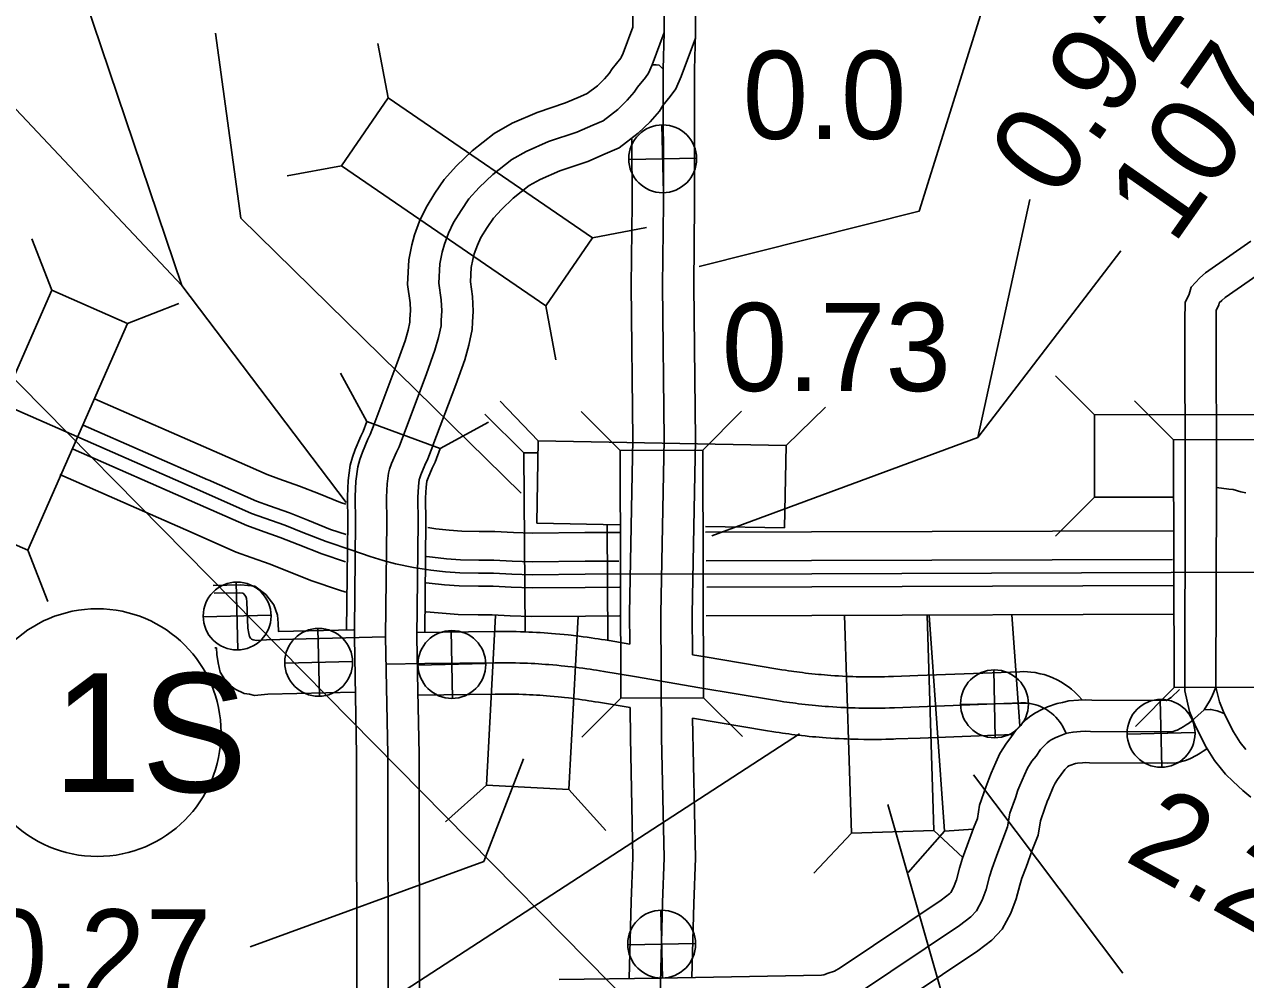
# Model space of a CAD drawing. Extents: x 31699 to 244310, y -8841 to 11474.
# Drawn here: x 100385.5 to 100776, y 2787.2 to 3092.6 of the extents above; entities that cross this region are included whole.
import ezdxf

# ---------------------------------------------------------------- set-up
doc = ezdxf.new("R2010")
doc.units = 0
for name, color, linetype in [('B_Logo', 7, 'Continuous'), ('G-ANNO-TEXT', 7, 'Continuous'), ('Level 21', 7, 'Continuous'), ('Level 48', 7, 'Continuous'), ('New Level (0)', 7, 'Continuous'), ('R_Border Notes', 7, 'Continuous'), ('R_XS_EARTHWORK_STAGE1', 7, 'Continuous'), ('R_XS_EARTHWORK_STAGE2', 7, 'Continuous'), ('S_WALL', 7, 'Continuous'), ('S_WALL_ANNOT', 7, 'Continuous')]:
    doc.layers.add(name, color=color, linetype=linetype)

msp = doc.modelspace()

# ---------------------------------------------------------------- linework, layer by layer
at = {"layer": 'B_Logo'}
for points in [[(100501.85, 2777.7), (100501.71, 2859.16), (100501.02, 2896.74), (100501.41, 2933.6), (100501.3, 2941.48), (100501.5, 2945.69), (100501.92, 2949.1), (100502.3, 2950.37), (100502.94, 2952.19), (100504.48, 2955.82), (100505.32, 2957.56), (100514.03, 2980.87), (100516.79, 2988.39), (100517.92, 2992.48), (100518.73, 2996.23), (100518.78, 2997.9), (100519, 3001.05), (100518.81, 3004.58), (100518.07, 3009.85), (100518.38, 3016.06), (100519.12, 3019.81), (100519.82, 3022.29), (100521.09, 3025.85), (100522.71, 3029.28), (100525.12, 3033.13), (100527.66, 3036.84), (100530.87, 3040.43), (100535.27, 3044.64), (100541.32, 3049.4), (100545.95, 3052.01), (100553.09, 3055.13), (100562.1, 3058.14), (100567.27, 3060.36), (100570.57, 3061.82), (100575.25, 3065.43), (100578.27, 3068.35), (100580.5, 3070.92), (100581.54, 3072.54), (100584.09, 3075.65), (100585.07, 3077), (100586.23, 3079.69), (100590.07, 3089.96), (100589.99, 3104.52)], [(100588.68, 2777.59), (100589.51, 2811.79), (100590.1, 2826.09), (100589.26, 2864.6), (100589.01, 2904.13), (100590.06, 2959.83), (100589.53, 3009.1), (100589.81, 3035.34), (100589.71, 3078.34), (100590.07, 3089.96)], [(100589.71, 3078.34), (100588.42, 3079.59), (100587.56, 3079.71), (100586.23, 3079.69)], [(100783.36, 3015.01), (100769.38, 3005.31), (100768.33, 3004.36), (100767.54, 3003.55), (100767.36, 3002.81), (100766.58, 3001.26), (100766.56, 2998.06), (100766.62, 2944.57), (100766.49, 2880.67), (100767.63, 2875.95), (100769.08, 2872.3), (100772.1, 2866.4), (100774.21, 2863.03), (100776.04, 2860.79)], [(100348.06, 2984.62), (100442.54, 2943.16)], [(100776.03, 2942.78), (100774.49, 2943.09), (100772.02, 2943.86), (100770.62, 2944.04), (100766.62, 2944.57)], [(100780.93, 2917.42), (100637.24, 2916.97), (100564.79, 2916.77), (100547.88, 2916.63), (100541.35, 2916.8), (100535.48, 2917.11), (100530.75, 2917.17), (100524.76, 2917.27), (100520.16, 2917.6), (100515.42, 2918.06), (100509.95, 2918.91), (100504.14, 2920.09), (100500.26, 2921.23), (100496.11, 2922.5), (100490.16, 2924.48), (100481.99, 2927.22), (100474.56, 2930.17), (100468.8, 2932.49), (100462.44, 2934.72), (100458.15, 2936.26), (100442.54, 2943.16)], [(100501.02, 2896.74), (100462.88, 2895.87), (100459.75, 2895.62), (100459.15, 2895.74), (100458.68, 2895.8), (100458.15, 2896.06), (100457.81, 2896.32), (100457.47, 2896.85), (100457.26, 2897.85), (100456.96, 2899.58), (100456.64, 2907.99), (100456.56, 2909.06), (100456.35, 2909.66), (100455.94, 2910.18), (100455.67, 2910.51), (100455.33, 2910.78), (100454.27, 2910.89), (100446.15, 2910.7)], [(100501.05, 2888.02), (100513.58, 2888.2), (100535.97, 2888.47), (100537.22, 2888.48), (100538.34, 2888.48), (100539.43, 2888.48), (100540.49, 2888.47), (100541.35, 2888.46), (100542.55, 2888.44), (100543.88, 2888.4), (100545.23, 2888.36), (100546.38, 2888.31), (100547.54, 2888.26), (100548.67, 2888.2), (100549.86, 2888.13), (100550.98, 2888.06), (100552.11, 2887.98), (100553.24, 2887.9), (100554.46, 2887.8), (100555.79, 2887.68), (100557.12, 2887.55), (100558.27, 2887.44), (100559.27, 2887.33), (100560.62, 2887.17), (100561.68, 2887.05), (100562.86, 2886.9), (100564.06, 2886.74), (100565.3, 2886.56), (100566.41, 2886.4), (100567.49, 2886.24), (100568.46, 2886.09), (100569.57, 2885.9), (100570.78, 2885.7), (100580.63, 2884.04), (100601.52, 2880.52), (100624.73, 2876.61), (100624.73, 2876.61), (100626.1, 2876.39), (100627.31, 2876.2), (100628.33, 2876.04), (100629.3, 2875.9), (100630.19, 2875.77), (100631.2, 2875.64), (100632.1, 2875.52), (100633.03, 2875.4), (100634.05, 2875.28), (100635.13, 2875.15), (100636.22, 2875.03), (100637.39, 2874.91), (100638.46, 2874.81), (100639.41, 2874.72), (100640.48, 2874.63), (100641.5, 2874.55), (100642.59, 2874.46), (100643.97, 2874.37), (100645.26, 2874.29), (100646.56, 2874.22), (100648, 2874.15), (100648.82, 2874.11), (100650.02, 2874.07), (100651.17, 2874.03), (100652.31, 2874), (100654, 2873.98), (100655.77, 2873.96), (100657.07, 2873.96), (100658.18, 2873.97), (100659.39, 2873.98), (100660.72, 2874.01), (100662.1, 2874.04), (100663.09, 2874.08), (100663.73, 2874.1), (100671.57, 2874.4), (100704.09, 2875.64), (100704.88, 2875.65), (100705.59, 2875.62), (100706.24, 2875.57), (100707, 2875.47), (100708.01, 2875.24), (100708.85, 2875.05), (100709.59, 2874.8), (100710.34, 2874.49), (100711.2, 2874.1), (100712.04, 2873.64), (100712.71, 2873.22), (100713.31, 2872.81), (100713.87, 2872.36), (100714.6, 2871.72), (100715.27, 2871.09), (100715.89, 2870.39), (100716.45, 2869.71), (100716.99, 2868.91), (100717.49, 2868.13), (100718.52, 2866.11)], [(100766.49, 2880.67), (100765.14, 2877.58), (100764.43, 2876.17), (100762.67, 2873.47), (100758.66, 2869.8), (100758.07, 2869.32), (100757.01, 2868.64), (100756.02, 2868.02), (100755.3, 2867.54), (100754.11, 2866.92), (100753.71, 2866.78), (100752.45, 2866.43), (100750.85, 2866.41), (100726.41, 2866.49), (100724.81, 2866.6), (100723.22, 2866.51), (100720.82, 2866.33), (100719.49, 2866.05), (100718.5, 2865.83), (100716.38, 2865.06), (100715.12, 2864.51), (100713.8, 2863.82), (100713.14, 2863.41), (100712.48, 2862.86), (100711.63, 2862.05), (100710.38, 2860.7), (100708.95, 2858.67), (100707.64, 2856.98), (100706.21, 2854.75), (100705.31, 2852.67), (100703.83, 2849.24), (100703.18, 2847.7), (100702.35, 2845.35), (100700.63, 2840.44), (100699.89, 2836.03), (100698.35, 2832.06), (100696.37, 2826.62), (100694.96, 2822.79), (100694.13, 2820.11), (100693.06, 2816.02), (100691.72, 2812.53), (100689.97, 2809.16), (100688.13, 2807.26), (100684.51, 2804.47), (100651.54, 2782.38)], [(100769.08, 2872.3), (100766.87, 2873.13), (100765.8, 2873.38), (100765, 2873.5), (100764.6, 2873.5), (100762.67, 2873.47)]]:
    msp.add_lwpolyline(points, dxfattribs=at)
at = {"layer": 'G-ANNO-TEXT'}
msp.add_line((100633.38, 2865.75), (100310.14, 2655.9), dxfattribs=at)
msp.add_lwpolyline([(100601.26, 3015.16), (100671.57, 3032.86), (100704.46, 3137.9)], dxfattribs=at)
at = {"layer": 'Level 21'}
for p, q in [((100589.84, 3038.78), (100589.34, 3060.48)), ((100578.74, 3049.38), (100600.44, 3049.88)), ((100453.77, 2892.57), (100453.27, 2914.27)), ((100442.67, 2903.17), (100464.37, 2903.67)), ((100479.87, 2877.77), (100479.37, 2899.47)), ((100522.43, 2877.1), (100521.93, 2898.8)), ((100468.78, 2888.37), (100490.47, 2888.87)), ((100511.33, 2887.7), (100533.02, 2888.2)), ((100695.93, 2864.49), (100695.43, 2886.19)), ((100684.83, 2875.09), (100706.53, 2875.59)), ((100749.19, 2855.09), (100748.68, 2876.78)), ((100738.09, 2865.69), (100759.78, 2866.19)), ((100589.53, 2787.67), (100589.03, 2809.37)), ((100578.43, 2798.27), (100600.13, 2798.77))]:
    msp.add_line(p, q, dxfattribs=at)
for centre in [(100589.59, 3049.63), (100453.52, 2903.42), (100479.62, 2888.62), (100522.18, 2887.95), (100695.68, 2875.34), (100748.94, 2865.94), (100589.28, 2798.52)]:
    msp.add_circle(centre, 10.85, dxfattribs=at)
at = {"layer": 'Level 48'}
msp.add_line((100000.09, 3366.76), (102655.5, 673.93), dxfattribs=at)
at = {"layer": 'New Level (0)'}
for points in [[(100407.92, 2972.91), (100447.9, 2955.37)], [(100404.26, 2964.51), (100444.21, 2946.97)], [(100401.08, 2956.81), (100440.86, 2939.34)], [(100488.27, 2939.17), (100486.58, 2939.74), (100479.51, 2942.56), (100473.5, 2944.97), (100466.9, 2947.29), (100463.1, 2948.65), (100447.93, 2955.35)], [(100396.86, 2948.65), (100437.18, 2930.95)], [(100488.38, 2929.47), (100483.43, 2931.13), (100476.11, 2934.04), (100470.27, 2936.39), (100463.83, 2938.65), (100459.7, 2940.13), (100444.22, 2946.97)], [(100488.22, 2920.73), (100480.56, 2923.3), (100473.01, 2926.3), (100467.33, 2928.59), (100461.05, 2930.8), (100456.61, 2932.39), (100440.85, 2939.35)], [(100488.33, 2911.03), (100485.94, 2911.83), (100477.41, 2914.69), (100469.61, 2917.79), (100464.1, 2920.01), (100457.98, 2922.16), (100453.21, 2923.87), (100437.15, 2930.96)], [(100576.1, 2930.13), (100564.72, 2930.1), (100547.99, 2929.97), (100541.87, 2930.12), (100535.92, 2930.44), (100530.96, 2930.5), (100525.35, 2930.6), (100521.28, 2930.89), (100517.09, 2931.3), (100514.52, 2931.69)], [(100752.76, 2930.67), (100637.2, 2930.3), (100603.32, 2930.21)], [(100575.56, 2920.96), (100564.77, 2920.93), (100547.91, 2920.8), (100541.51, 2920.96), (100535.62, 2921.27), (100530.82, 2921.33), (100524.94, 2921.44), (100520.51, 2921.75), (100515.95, 2922.2), (100514.1, 2922.48)], [(100752.58, 2921.5), (100637.22, 2921.14), (100603.5, 2921.04)], [(100575.74, 2912.63), (100564.81, 2912.6), (100547.84, 2912.47), (100541.19, 2912.64), (100535.35, 2912.94), (100530.69, 2913), (100524.57, 2913.11), (100519.81, 2913.45), (100514.9, 2913.93), (100513.95, 2914.07)], [(100752.76, 2913.17), (100637.25, 2912.8), (100603.68, 2912.71)], [(100575.74, 2903.46), (100564.86, 2903.43), (100547.76, 2903.3), (100540.83, 2903.47), (100535.05, 2903.78), (100530.55, 2903.84), (100524.17, 2903.95), (100519.04, 2904.31), (100513.94, 2904.81)], [(100752.93, 2904), (100637.28, 2903.64), (100603.5, 2903.54)]]:
    msp.add_lwpolyline(points, dxfattribs=at)
at = {"layer": 'R_Border Notes'}
msp.add_circle((100408.8, 2866.15), 39.6, dxfattribs=at)
at = {"layer": 'R_XS_EARTHWORK_STAGE1'}
for p, q in [((100501.8, 3069.16), (100498.56, 3086.46)), ((100486.88, 3047.38), (100469.58, 3044.15)), ((100567.15, 3024.41), (100584.45, 3027.65)), ((100394.27, 3007.59), (100387.87, 3023.99)), ((100418.44, 2996.98), (100434.84, 3003.38)), ((100552.23, 3002.63), (100555.46, 2985.33)), ((100494.99, 2965.63), (100486.56, 2981.08)), ((100727.6, 2967.81), (100715.15, 2980.24)), ((100549.83, 2959.48), (100537.62, 2972.16)), ((100752.9, 2959.8), (100740.42, 2972.21)), ((100545.23, 2955.6), (100532.68, 2967.95)), ((100575.98, 2956.4), (100563.5, 2968.81)), ((100602.38, 2956.47), (100614.79, 2968.95)), ((100629.02, 2958), (100641.69, 2970.21)), ((100806.8, 2967.89), (100727.6, 2967.81)), ((100727.6, 2967.81), (100727.63, 2941.41)), ((100494.99, 2965.63), (100518.46, 2957.02)), ((100518.46, 2957.02), (100533.91, 2965.44)), ((100549.83, 2959.48), (100549.34, 2933.09)), ((100629.02, 2958), (100549.83, 2959.48)), ((100549.42, 2955.64), (100545.23, 2955.6)), ((100545.23, 2955.6), (100545.67, 2898.42)), ((100628.52, 2931.6), (100629.02, 2958)), ((100727.63, 2941.41), (100715.2, 2928.95)), ((100727.63, 2941.41), (100753.11, 2941.43)), ((100549.34, 2933.09), (100575.92, 2932.59)), ((100572.1, 2895.64), (100571.81, 2932.4)), ((100603.32, 2932.08), (100628.52, 2931.6)), ((100386.61, 2924.46), (100393, 2908.06)), ((100753.15, 2880.6), (100740.75, 2868.12)), ((100576.2, 2877.2), (100563.79, 2864.72)), ((100602.6, 2877.27), (100615.08, 2864.86)), ((100533.25, 2849.37), (100520.16, 2837.61)), ((100559.62, 2847.96), (100571.37, 2834.86)), ((100679.66, 2834.67), (100668.12, 2821.38)), ((100676.33, 2834.87), (100685.56, 2826.2)), ((100649.94, 2834.04), (100637.89, 2821.22))]:
    msp.add_line(p, q, dxfattribs=at)
for points in [[(100567.15, 3024.41), (100501.8, 3069.16), (100486.88, 3047.38), (100552.23, 3002.63)], [(100386.61, 2924.46), (100418.44, 2996.98), (100394.27, 3007.59), (100362.43, 2935.07)], [(100752.9, 2959.8), (100753.15, 2880.6), (100779.55, 2880.68), (100779.3, 2959.88)], [(100575.98, 2956.4), (100576.2, 2877.2), (100602.6, 2877.27), (100602.38, 2956.47)]]:
    msp.add_lwpolyline(points, close=True, dxfattribs=at)
for points in [[(100488.55, 2898.94), (100488.91, 2933.57), (100488.79, 2941.69), (100489.04, 2946.75), (100489.64, 2951.66), (100490.41, 2954.24), (100491.28, 2956.72), (100493.09, 2960.97), (100493.81, 2962.47), (100494.99, 2965.63)], [(100513.54, 2898.2), (100513.91, 2933.63), (100513.8, 2941.27), (100513.96, 2944.63), (100514.19, 2946.53), (100514.59, 2947.66), (100515.87, 2950.66), (100516.83, 2952.66), (100518.46, 2957.02)], [(100536.17, 2903.59), (100533.25, 2849.37), (100559.62, 2847.96), (100562.59, 2903.42)], [(100647.76, 2903.67), (100649.94, 2834.04), (100676.33, 2834.87), (100674.17, 2903.75)], [(100674.78, 2903.75), (100679.66, 2834.67), (100688.89, 2835.32)], [(100703.75, 2868.29), (100701.24, 2903.84)]]:
    msp.add_lwpolyline(points, dxfattribs=at)
at = {"layer": 'R_XS_EARTHWORK_STAGE2'}
for points in [[(100497.35, 2964.82), (100504.65, 2984.34), (100507.26, 2991.46), (100508.21, 2994.88), (100508.76, 2997.43), (100508.78, 2998.38), (100508.98, 3001.13), (100508.85, 3003.62), (100508.03, 3009.39), (100508.42, 3017.29), (100509.39, 3022.14), (100510.28, 3025.34), (100511.84, 3029.68), (100513.92, 3034.08), (100516.75, 3038.61), (100519.77, 3043.02), (100523.67, 3047.38), (100528.7, 3052.19), (100535.74, 3057.74), (100541.48, 3060.97), (100549.5, 3064.47), (100558.54, 3067.5), (100563.28, 3069.53), (100565.43, 3070.48), (100568.7, 3073), (100571, 3075.23), (100572.47, 3076.93), (100573.44, 3078.43), (100576.17, 3081.76), (100576.32, 3081.97), (100576.95, 3083.42), (100580.06, 3091.75), (100579.99, 3104.48)], [(100516.14, 2957.95), (100523.41, 2977.4), (100526.31, 2985.33), (100527.64, 2990.08), (100528.71, 2995.04), (100528.77, 2997.43), (100529.01, 3000.96), (100528.77, 3005.55), (100528.1, 3010.3), (100528.33, 3014.83), (100528.85, 3017.48), (100529.35, 3019.25), (100530.34, 3022.02), (100531.5, 3024.48), (100533.48, 3027.64), (100535.54, 3030.65), (100538.06, 3033.47), (100541.83, 3037.08), (100546.91, 3041.07), (100550.42, 3043.05), (100556.68, 3045.79), (100565.67, 3048.79), (100571.25, 3051.19), (100575.72, 3053.15), (100581.8, 3057.85), (100585.54, 3061.47), (100588.52, 3064.91), (100589.63, 3066.64), (100592.01, 3069.54), (100593.81, 3072.03), (100595.51, 3075.96), (100600.08, 3088.18), (100599.99, 3104.55)], [(100599.1, 2891.07), (100599.01, 2904.06), (100600.06, 2959.79), (100599.53, 3009.1), (100599.81, 3035.3), (100599.71, 3078.2), (100600.07, 3089.65)], [(100579.07, 2894.44), (100579.01, 2904.19), (100580.06, 2959.87), (100579.53, 3009.1), (100579.81, 3035.38), (100579.76, 3055.88)], [(100777.67, 3023.24), (100763.15, 3013.16), (100761.38, 3011.55), (100758.51, 3008.59), (100757.93, 3006.33), (100756.59, 3003.66), (100756.56, 2998.08), (100756.62, 2944.58), (100756.49, 2879.5), (100758.07, 2872.92), (100759.96, 2868.16), (100763.39, 2861.46), (100766.07, 2857.19), (100768.26, 2854.5), (100769.57, 2852.87), (100772.02, 2850.49), (100775.07, 2847.6), (100777.62, 2845.47)], [(100491.05, 2898.91), (100491.41, 2933.58), (100491.29, 2941.65), (100491.53, 2946.53), (100492.09, 2951.15), (100492.78, 2953.47), (100493.61, 2955.81), (100495.37, 2959.94), (100496.11, 2961.49), (100497.33, 2964.76)], [(100511.34, 2879.38), (100511.02, 2896.77), (100511.41, 2933.62), (100511.3, 2941.31), (100511.47, 2944.84), (100511.74, 2947.05), (100511.81, 2947.28), (100512.26, 2948.56), (100513.59, 2951.69), (100514.53, 2953.64), (100516.12, 2957.89)], [(100490.77, 2899.04), (100466.73, 2898.49), (100466.63, 2901.1), (100466.43, 2903.66), (100465.26, 2907.02), (100463.76, 2908.95), (100462.69, 2910.26), (100459.24, 2912.94), (100454.69, 2913.44), (100445.91, 2913.23)], [(100497.38, 2702.46), (100491.67, 2703.63), (100491.85, 2777.7), (100491.71, 2859.06), (100491.02, 2896.7), (100491.05, 2898.91)], [(100511, 2898.17), (100535.87, 2898.47), (100537.17, 2898.48), (100538.34, 2898.48), (100539.49, 2898.48), (100540.6, 2898.47), (100541.52, 2898.46), (100542.77, 2898.43), (100544.17, 2898.4), (100545.59, 2898.35), (100546.8, 2898.3), (100548.02, 2898.25), (100549.21, 2898.19), (100550.47, 2898.11), (100551.65, 2898.04), (100552.83, 2897.96), (100554.03, 2897.87), (100555.31, 2897.76), (100556.71, 2897.64), (100558.1, 2897.5), (100559.32, 2897.38), (100560.38, 2897.27), (100561.79, 2897.1), (100562.9, 2896.97), (100564.14, 2896.81), (100565.41, 2896.64), (100566.71, 2896.46), (100567.88, 2896.29), (100569.01, 2896.12), (100570.04, 2895.96), (100571.2, 2895.77), (100572.44, 2895.56), (100579.07, 2894.44)], [(100491.12, 2879.04), (100463.39, 2878.41), (100459.13, 2878.07), (100457.51, 2878.41), (100455.81, 2878.62), (100452.85, 2880.05), (100450.33, 2882.01), (100448.08, 2885.5), (100447.43, 2888.5), (100447, 2891.09), (100446.91, 2893.25), (100446.38, 2893.23)], [(100599.1, 2891.07), (100603.19, 2890.38), (100626.37, 2886.48), (100627.69, 2886.26), (100628.84, 2886.08), (100629.8, 2885.93), (100630.73, 2885.8), (100631.56, 2885.68), (100632.52, 2885.55), (100633.38, 2885.44), (100634.25, 2885.33), (100635.22, 2885.21), (100636.25, 2885.09), (100637.28, 2884.98), (100638.39, 2884.86), (100639.4, 2884.76), (100640.3, 2884.68), (100641.31, 2884.59), (100642.28, 2884.52), (100643.32, 2884.44), (100644.63, 2884.35), (100645.85, 2884.27), (100647.07, 2884.2), (100648.45, 2884.14), (100649.22, 2884.1), (100650.36, 2884.06), (100651.45, 2884.03), (100652.52, 2884), (100654.12, 2883.97), (100655.81, 2883.96), (100657.04, 2883.96), (100658.09, 2883.97), (100659.24, 2883.98), (100660.5, 2884), (100661.81, 2884.04), (100662.75, 2884.07), (100663.35, 2884.09), (100671.19, 2884.39), (100703.83, 2885.63), (100704.98, 2885.65), (100706.19, 2885.61), (100707.33, 2885.51), (100708.73, 2885.32), (100710.23, 2884.99), (100711.58, 2884.68), (100713.06, 2884.18), (100714.29, 2883.68), (100715.68, 2883.05), (100717.13, 2882.26), (100718.22, 2881.57), (100719.3, 2880.83), (100720.3, 2880.02), (100721.32, 2879.12), (100722.44, 2878.07), (100723.8, 2876.56)], [(100511.45, 2660.2), (100512.55, 2666.96), (100514.35, 2680.87), (100520.01, 2718.27), (100511.7, 2719.96), (100511.85, 2777.69), (100511.71, 2859.26), (100511.34, 2879.38)], [(100511.36, 2878.17), (100536.08, 2878.47), (100537.28, 2878.48), (100538.34, 2878.48), (100539.37, 2878.48), (100540.38, 2878.47), (100541.19, 2878.46), (100542.32, 2878.44), (100543.58, 2878.41), (100544.87, 2878.36), (100545.96, 2878.32), (100547.05, 2878.27), (100548.13, 2878.22), (100549.26, 2878.15), (100550.32, 2878.08), (100551.39, 2878.01), (100552.46, 2877.93), (100553.61, 2877.83), (100554.88, 2877.72), (100556.14, 2877.6), (100557.23, 2877.49), (100558.17, 2877.39), (100559.46, 2877.24), (100560.45, 2877.12), (100561.57, 2876.98), (100562.71, 2876.83), (100563.88, 2876.66), (100564.94, 2876.51), (100565.96, 2876.36), (100566.87, 2876.21), (100567.93, 2876.04), (100569.12, 2875.84), (100579.2, 2874.14)], [(100754.88, 2879.89), (100752.18, 2877.42), (100751.65, 2877.08), (100750.63, 2876.44), (100750.57, 2876.41), (100726.77, 2876.49), (100724.86, 2876.62), (100722.57, 2876.48), (100719.4, 2876.26), (100717.37, 2875.82), (100715.72, 2875.46), (100712.66, 2874.35), (100710.79, 2873.53), (100708.84, 2872.51), (100707.28, 2871.54), (100705.83, 2870.34), (100704.49, 2869.06), (100702.59, 2866.99), (100700.91, 2864.62), (100699.47, 2862.76), (100697.36, 2859.48), (100696.13, 2856.64), (100694.62, 2853.15), (100693.85, 2851.29), (100692.92, 2848.67), (100690.91, 2842.94), (100690.2, 2838.68), (100688.99, 2835.59), (100686.98, 2830.06), (100685.48, 2825.99), (100684.51, 2822.85), (100683.53, 2819.1), (100682.59, 2816.64), (100681.77, 2815.07), (100681.45, 2814.74), (100678.67, 2812.59), (100646.32, 2790.93), (100644.49, 2789.91), (100642.47, 2789.22), (100641.14, 2788.7), (100640.37, 2788.6), (100588.52, 2787.59), (100556.53, 2787.18)], [(100578.92, 2787.54), (100579.51, 2812.12), (100580.09, 2826.19), (100579.26, 2864.46), (100579.2, 2874.14)], [(100598.93, 2787.87), (100599.5, 2811.47), (100600.1, 2825.99), (100599.13, 2870.78)], [(100599.13, 2870.78), (100623.08, 2866.75), (100624.51, 2866.51), (100625.78, 2866.31), (100626.85, 2866.15), (100627.88, 2866), (100628.81, 2865.87), (100629.88, 2865.72), (100630.83, 2865.6), (100631.8, 2865.48), (100632.87, 2865.35), (100634.02, 2865.22), (100635.16, 2865.09), (100636.39, 2864.96), (100637.52, 2864.85), (100638.51, 2864.76), (100639.64, 2864.66), (100640.72, 2864.58), (100641.87, 2864.49), (100643.32, 2864.39), (100644.67, 2864.31), (100646.04, 2864.23), (100647.55, 2864.16), (100648.43, 2864.12), (100649.68, 2864.07), (100650.89, 2864.04), (100652.1, 2864.01), (100653.87, 2863.98), (100655.73, 2863.96), (100657.1, 2863.96), (100658.27, 2863.97), (100659.55, 2863.98), (100660.95, 2864.01), (100662.39, 2864.05), (100663.43, 2864.08), (100664.1, 2864.11), (100671.95, 2864.4), (100701.56, 2865.53)], [(100763.58, 2860.98), (100762.38, 2860.2), (100761.42, 2859.6), (100760.38, 2858.91), (100758.1, 2857.73), (100756.72, 2857.24), (100753.9, 2856.45), (100750.91, 2856.4), (100726.06, 2856.49), (100724.76, 2856.58), (100723.86, 2856.53), (100722.25, 2856.41), (100721.61, 2856.27), (100721.27, 2856.2), (100720.1, 2855.78), (100719.45, 2855.49), (100718.98, 2855.24), (100718.77, 2855.04), (100718.18, 2854.4), (100716.99, 2852.72), (100715.82, 2851.2), (100715.06, 2850.03), (100714.49, 2848.7), (100713.03, 2845.34), (100712.52, 2844.11), (100711.78, 2842.02), (100710.35, 2837.95), (100709.59, 2833.37), (100707.71, 2828.54), (100705.76, 2823.18), (100704.44, 2819.59), (100703.75, 2817.37), (100702.59, 2812.95), (100700.85, 2808.41), (100698.17, 2803.26), (100694.81, 2799.79), (100690.35, 2796.35), (100656.76, 2773.84)]]:
    msp.add_lwpolyline(points, dxfattribs=at)
at = {"layer": 'S_WALL'}
for p, q in [((100435.88, 3009.12), (100404.95, 3100.62)), ((100690.35, 2960.49), (100706.99, 3036.65)), ((100688.99, 2852.69), (100736.74, 2789.27)), ((100661.62, 2843.19), (100688.99, 2747.26))]:
    msp.add_line(p, q, dxfattribs=at)
for points in [[(100544.39, 2942.69), (100454.71, 3030.65), (100446.64, 3089.85)], [(100367.3, 3081.78), (100435.88, 3009.12), (100488.39, 2939.74)], [(100605.31, 2929.11), (100690.35, 2960.49), (100736.08, 3020.2)], [(100545.12, 2857.76), (100532.38, 2824.98), (100457.75, 2797.66)]]:
    msp.add_lwpolyline(points, dxfattribs=at)

# ---------------------------------------------------------------- texts
at = {"layer": 'R_Border Notes'}
msp.add_text('1S', height=38.016, dxfattribs=at).set_placement((100394.62, 2847.14))
at = {"layer": 'S_WALL'}
for s, height, p in [('107.01(U.P.)', 28.1599, (100752.93, 3021.76)), ('0.92(O.P.)', 28.16, (100715.46, 3036))]:
    msp.add_text(s, height=height, rotation=55, dxfattribs=at).set_placement(p)
msp.add_text('0.73', height=28.16, dxfattribs=at).set_placement((100608.47, 2975.37))
at = {"layer": 'S_WALL_ANNOT'}
for s, p in [('0.0', (100615.16, 3055.98)), ('0.27', (100371.92, 2781.47))]:
    msp.add_text(s, height=28.16, dxfattribs=at).set_placement(p)
msp.add_text('2.22', height=28.16, rotation=331, dxfattribs=at).set_placement((100736.67, 2825.53))

doc.saveas('drawing.dxf')
